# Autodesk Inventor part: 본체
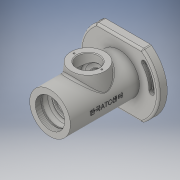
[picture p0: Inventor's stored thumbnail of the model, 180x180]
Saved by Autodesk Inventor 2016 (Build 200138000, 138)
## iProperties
Created: 2022-05
Part Number: 본체
Material: 일반
Document SubType Name: Modeling
Designer: PC-1-3
Density: 1 g/cm^3
Appearance: 기본값
Author: PC-1-3
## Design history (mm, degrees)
sketch "스케치2"
  geometry: L1 (0, 51)-(30, 51); L2 (30, 51)-(30, -51); L3 (30, -51)-(0, -51); L4 (0, -51)-(0, 51); L5 (0, -71.4)-(0, 71.4) reference; L6 (-6, 0)-(36, 0) reference; 1 further point
  constraints: 8 end point, 3 perpendicular, 1 horizontal, 1 point on line, 1 other
  dimensions: "d1" = 60 diameter of L2 L5; "d2" = 102 distance of L1.end L2.end
revolve "회전1" sketch "스케치2" stored, may be unused: angle "d3" = 90 deg
sketch "스케치3"
  geometry: L1 (33.985, -47)-(-33.985, -47); L2 (-33.985, -47)-(-33.985, 47); L3 (-33.985, 47)-(33.985, 47); L4 (33.985, 47)-(33.985, -47); L5 (33.985, -47)-(-33.985, 47); L6 (-33.985, -47)-(33.985, 47); A1 r 58 centre (0, 0) between (33.985, -47) and (33.985, 47); A2 r 58 centre (0, 0) between (-33.985, 47) and (-33.985, -47); 1 further point
  constraints: 12 end point, 4 point on circle, 3 midpoint, 2 centre point, 2 parallel, 1 horizontal, 1 perpendicular
  dimensions: "d6" = 94 distance of L1.end L2.end; "d7" = 58 radius of A2; "d8" = 58 radius of A1
extrude "돌출1" join sketch "스케치3" distance "d9" = 13; taper "d10" = 0 deg
sketch "스케치4"
  geometry: C1 r 36 at (0, 0); 1 further point
  constraints: 1 centre point, 1 coincident
  dimensions: "d11" = 72 diameter of C1
extrude "돌출2" join sketch "스케치4" distance "d12" = 3; taper "d13" = 0 deg
node "작업 평면1"
sketch "스케치5"
  geometry: L1 (-30, 51)-(30, 51) reference; C1 r 25 at (0, -5); 1 further point
  constraints: 1 centre point, 1 vertical alignment
  dimensions: "d15" = 50 diameter of C1; "d69" = 56 distance from line of L1 C1.centre
extrude "돌출3" join sketch "스케치5" stored distance "d16" = 3; taper "d17" = 0 deg
feature "면 기울기1" dims angle "d18" = 5 deg
sketch "스케치7"
  geometry: 2 further points
  constraints: 1 coincident
hole "구멍1" sketch "스케치7" at (0, 0) diameter "d19" = 43.376; stored, may be unused: countersink angle "d23" = 90 deg, drill point angle "d25" = 0 deg; dims "d20" = 8, "d21" = 4, "d22" = 2, "d24" = 8
sketch "스케치10"
  geometry: C1 r 24 at (0, 0); 1 further point
  constraints: 1 centre point, 1 coincident
  dimensions: "d26" = 48 diameter of C1
extrude "돌출4" cut sketch "스케치10" distance "d27" = 3; taper "d28" = 0 deg
sketch "스케치11"
  geometry: C1 r 22.5 at (0, 0); 1 further point
  constraints: 1 centre point, 1 coincident
  dimensions: "d29" = 45 diameter of C1
extrude "돌출5" cut sketch "스케치11" distance "d30" = 11; taper "d31" = 0 deg
sketch "스케치15"
  geometry: L1 (17.5, 29)-(17.5, 26.75); L2 (17.5, 26.75)-(18.5, 26.75); L3 (18.5, 26.75)-(18.5, 25); L4 (18.5, 25)-(17.5, 25); L5 (17.5, 25)-(17.5, 15); L6 (18.5, 14)-(24, 14); L7 (27, 11)-(27, -21); L8 (24, -24)-(18.5, -24); L9 (17.5, -25)-(17.5, -34.4); L10 (16.9, -35)-(15, -35); L11 (15, -35)-(15, -37); L12 (12, -40)-(11, -40); L13 (11, -40)-(11, -45.7); L14 (11, -45.7)-(14.5, -45.7); L15 (15, -46.2)-(15, -52.3); L16 (0, -90.6)-(0, 74.6) reference; L17 (-22.5, 29)-(22.5, 29) reference; L18 (15.404, -53)-(18.456, -53); L19 (20.897, -54.256)-(30, -67); L20 (-36, -67)-(36, -67) reference; L21 (18.5, -24)-(17.5, -25); L22 (15, -52.3)-(15.404, -53); L23 (18.5, 14)-(17.5, 15); L24 (17.5, 29)-(0, 29); L25 (0, 29)-(0, -67); L26 (0, -67)-(30, -67); A1 r 0.5 centre (14.5, -46.2) between (15, -46.2) and (14.5, -45.7); A2 r 3 centre (12, -37) between (12, -40) and (15, -37); A3 r 0.6 centre (16.9, -34.4) between (16.9, -35) and (17.5, -34.4); A4 r 3 centre (24, -21) between (24, -24) and (27, -21); A5 r 3 centre (18.456, -56) between (20.897, -54.256) and (18.456, -53); A6 r 3 centre (24, 11) between (27, 11) and (24, 14); 10 further points
  constraints: 46 end point, 22 point on line, 13 perpendicular, 12 point on circle, 12 tangent, 6 centre point, 2 equal radius, 2 midpoint, 2 vertical, 1 horizontal
  dimensions: "d38" = 35 diameter of L1 L16; "d39" = 37 diameter of L3 L16; "d40" = 1.75 distance of L2.end L3.end; "d41" = 4 vertical distance of L1.start L3.end; "d42" = 11 distance of L4.end point (17.5, 14); "d43" = 54 diameter of L7 L16; "d44" = 35 diameter of L9 L16; "d45" = 38 distance of point (27, 14) point (27, -24); "d46" = 11 distance of point (17.5, -24) point (17.5, -35); "d47" = 5 distance of L10.end point (15, -40); "d48" = 30 diameter of L11 L16; "d49" = 22 diameter of L13 L16; "d50" = 30 diameter of L15 L16; "d51" = 40 diameter of point (20, -53) L16; "d52" = 60 diameter of L19.end L16; "d53" = 7.3 distance of point (15, -45.7) point (15, -53); "d54" = 14 vertical distance of point (20, -53) L19.end; "d55" = 0.5 radius of A1; "d56" = 3 radius of A2; "d57" = 0.6 radius of A3; "d58" = 1 distance of L8.end point (17.5, -24); "d59" = 1 distance of L9.start point (17.5, -24) (= d58); "d60" = 0.7 distance of L15.end point (15, -53); "d61" = 30 deg angle of L15 L22; "d62" = 3 radius of A5; "d63" = 1 distance of L6.start point (17.5, 14); "d64" = 1 distance of L5.end point (17.5, 14) (= d63)
revolve "회전2" sketch "스케치15" stored, may be unused: angle "d65" = 90 deg
sketch "스케치19"
  geometry: C1 r 25 at (0, 0) reference; C2 r 16 at (0, 0); 1 further point
  constraints: 1 centre point, 1 coincident
  dimensions: "d70" = 32 diameter of C2
extrude "돌출8" cut sketch "스케치19" stored distance "d71" = 0; taper "d72" = 0 deg
sketch "스케치22" dims "d73" = 41
  geometry: C1 r 16 at (0, 0) reference; C2 r 25 at (0, 0) reference; 3 further points
  constraints: 1 coincident, 1 horizontal alignment, 2 other
hole "구멍2" sketch "스케치22" at (-20.5, 0) diameter "d74" = 2.459; stored, may be unused: countersink angle "d78" = 90 deg, drill point angle "d80" = 118 deg; dims "d75" = 6, "d76" = 4, "d77" = 2, "d79" = 8
sketch "스케치23" dims "d84" = 96
  geometry: L1 (0, 0)-(36.77, 30.854); L2 (0, 0)-(48, 0); A1 r 48 centre (0, 0) between (48, 0) and (36.77, 30.854); A2 r 52 centre (0, 0) between (52, 0) and (39.834, 33.425); A3 r 44 centre (0, 0) between (44, 0) and (33.706, 28.283); A4 r 4 centre (48, 0) between (44, 0) and (52, 0); A5 r 4 centre (36.77, 30.854) between (39.834, 33.425) and (33.706, 28.283); 3 further points
  constraints: 10 point on circle, 5 centre point, 4 end point, 4 tangent, 3 coincident, 2 horizontal alignment, 1 horizontal, 3 other
  dimensions: "d85" = 40 deg angle of L2 L1; "d86" = 4 radius of A5
extrude "돌출9" cut sketch "스케치23" distance "d87" = 4.4; taper "d88" = 0 deg
sketch "스케치25"
  geometry: A1 r 52 centre (0, 0) between (52, 0) and (39.834, 33.425) reference; A2 r 4 centre (36.77, 30.854) between (39.834, 33.425) and (33.706, 28.283) reference; A3 r 44 centre (0, 0) between (44, 0) and (33.706, 28.283) reference; A4 r 4 centre (48, 0) between (44, 0) and (52, 0) reference; A5 r 50.25 centre (0, 0) between (50.25, 0) and (38.494, 32.3); A6 r 2.25 centre (48, 0) between (45.75, 0) and (50.25, 0); A7 r 45.75 centre (0, 0) between (45.75, 0) and (35.047, 29.408); A8 r 2.25 centre (36.77, 30.854) between (38.494, 32.3) and (35.047, 29.408); 1 further point
  constraints: 8 point on circle, 4 centre point, 3 other
  dimensions: "d100" = 2.25 radius of A8
extrude "돌출10" cut sketch "스케치25" stored distance "d101" = 4.4; taper "d102" = 0 deg
hole "구멍3" diameter "d91" = 8; stored, may be unused: countersink angle "d95" = 90 deg, drill point angle "d97" = 118 deg; dims "d92" = 6, "d93" = 4, "d94" = 2, "d96" = 8, "d98" = 10, "d99" = 10
fillet "모깎기1" dims "d106" = 3
chamfer "모따기2" distance "d107" = 1; stored, may be unused: second distance "d108" = 2, angle "d109" = 45 deg
fillet "모깎기2" dims "d110" = 3
fillet "모깎기3" dims "d111" = 3
chamfer "모따기3" distance "d112" = 1; stored, may be unused: second distance "d113" = 2, angle "d114" = 45 deg
node "작업 평면2"
sketch "스케치28"
  geometry: L1 (5, 23)-(5, -27); L2 (5, -27)-(-5, -27); L3 (-5, -27)-(-5, 23); L4 (-5, 23)-(5, 23); L5 (0, 23)-(0, -27); L6 (5, -2)-(-5, -2); L7 (0, -109.547)-(0, 188.285) reference; L8 (-46.4, -64)-(46.4, -64) reference; 2 further points
  constraints: 5 midpoint, 4 end point, 1 point on line, 2 other
  dimensions: "d125" = 50 distance of L1.start L1.end; "d126" = 10 distance of L1.end L2.end; "d127" = 62 distance from line of L8 point (0, -2)
feature "엠보싱1" sketch "스케치28" dims "d1" = 60, "d2" = 102, "d128" = 0.5, "d129" = 0
chamfer "모따기7" distance "d130" = 1; stored, may be unused: second distance "d131" = 2, angle "d132" = 45 deg
node "솔리드1"
pattern_circular "원형 패턴1" dims angle "d82" = 360 deg
pattern_circular "원형 패턴2" dims "d104" = 360 deg
node "투영된 루프1"
node "투영된 루프2"
node "투영된 루프3"
other parameters: "d14" = 38, "d124" = 82.25
